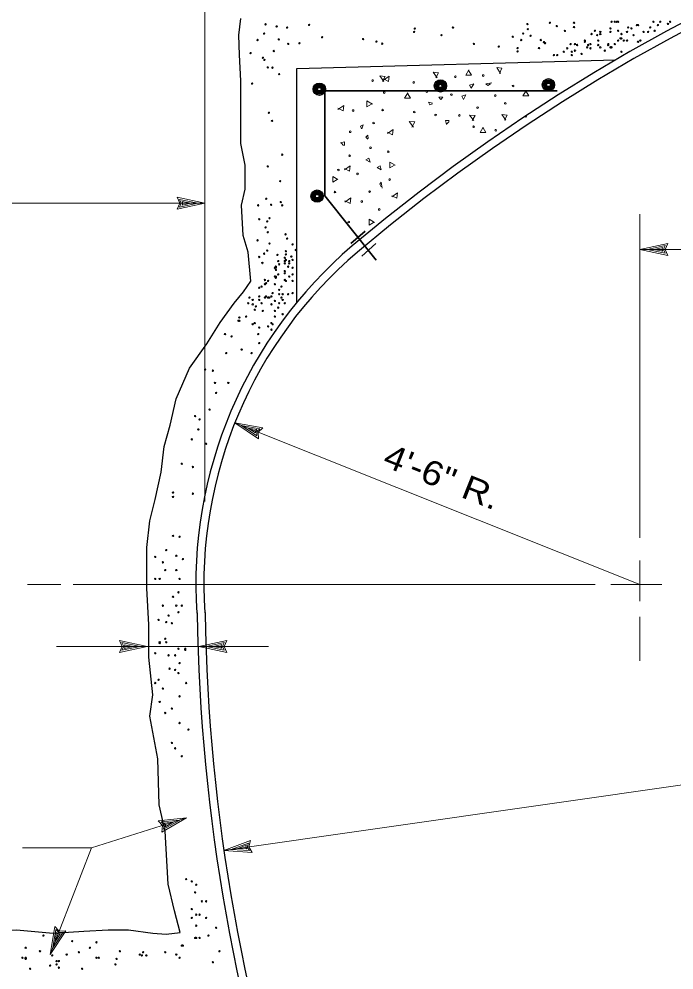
# Model space of a CAD drawing. Extents: x -24.3 to 17.7, y -17.6 to 12.4.
# Drawn here: x -17.912 to -14.525, y -10.053 to -5.135 of the extents above; entities that cross this region are included whole.
import ezdxf
from ezdxf.enums import TextEntityAlignment as Align

# ---------------------------------------------------------------- set-up
doc = ezdxf.new("R2010")
doc.units = 0
doc.header["$LTSCALE"] = 0.05
doc.layers.add('1', color=7, linetype='Continuous', lineweight=13)
doc.layers.add('2', color=7, linetype='Continuous', lineweight=13)

msp = doc.modelspace()

# ---------------------------------------------------------------- linework, layer by layer
at = {"layer": '1'}
for p, q in [((-16.95069, -7.6306), (-16.95069, -1.0886)), ((-19.95069, -6.0876), (-16.95069, -6.0876)), ((-16.95069, -6.0876), (-17.09469, -6.0566)), ((-16.95069, -6.0876), (-17.09469, -6.1186)), ((-16.98769, -6.0876), (-17.08169, -6.0676)), ((-17.07269, -6.0876), (-17.08169, -6.0676)), ((-16.98769, -6.0876), (-17.08169, -6.1076)), ((-17.08169, -6.1076), (-17.07269, -6.0876)), ((-17.02369, -6.0876), (-17.06869, -6.0786)), ((-17.06469, -6.0876), (-17.06869, -6.0786)), ((-17.02369, -6.0876), (-17.06869, -6.0976)), ((-17.06869, -6.0976), (-17.06469, -6.0876)), ((-14.70069, -7.8176), (-14.70069, -6.1446)), ((-14.70069, -6.3266), (-14.55669, -6.2956)), ((-14.70069, -6.3266), (-9.90769, -6.3266)), ((-14.70069, -6.3266), (-14.55669, -6.3576)), ((-14.66369, -6.3266), (-14.56969, -6.3066)), ((-14.66369, -6.3266), (-14.56969, -6.3466)), ((-14.62769, -6.3266), (-14.58269, -6.3166)), ((-14.62769, -6.3266), (-14.58269, -6.3356)), ((-14.58269, -6.3166), (-14.58669, -6.3266)), ((-14.58669, -6.3266), (-14.58269, -6.3356)), ((-14.56969, -6.3066), (-14.57869, -6.3266)), ((-14.57869, -6.3266), (-14.56969, -6.3466)), ((-16.79569, -7.2236), (-16.67369, -7.3056)), ((-16.76169, -7.2376), (-16.66669, -7.2536)), ((-16.76169, -7.2376), (-16.68169, -7.2906)), ((-16.72769, -7.2506), (-16.68969, -7.2756)), ((-16.72769, -7.2506), (-16.68269, -7.2576)), ((-16.68269, -7.2576), (-16.68969, -7.2656)), ((-16.68969, -7.2656), (-16.68969, -7.2756)), ((-16.66669, -7.2536), (-16.68269, -7.2686)), ((-16.68269, -7.2686), (-16.68169, -7.2906)), ((-14.70069, -8.1456), (-14.70069, -7.9356)), ((-17.86769, -8.0586), (-17.69669, -8.0586)), ((-17.63269, -8.0586), (-14.93269, -8.0586)), ((-14.85069, -8.0586), (-14.58769, -8.0586)), ((-14.70069, -8.4546), (-14.70069, -8.2266)), ((-17.24869, -8.3796), (-17.39269, -8.3486)), ((-17.28569, -8.3796), (-17.37969, -8.3596)), ((-17.37069, -8.3796), (-17.37969, -8.3596)), ((-16.98169, -8.3796), (-16.83769, -8.3486)), ((-16.94469, -8.3796), (-16.85069, -8.3596)), ((-16.85069, -8.3596), (-16.85969, -8.3796)), ((-17.24869, -8.3796), (-17.39269, -8.4106)), ((-17.28569, -8.3796), (-17.37969, -8.3996)), ((-17.37969, -8.3996), (-17.37069, -8.3796)), ((-17.32169, -8.3796), (-17.36669, -8.3706)), ((-17.36269, -8.3796), (-17.36669, -8.3706)), ((-17.32169, -8.3796), (-17.36669, -8.3896)), ((-17.36669, -8.3896), (-17.36269, -8.3796)), ((-16.98169, -8.3796), (-16.83769, -8.4106)), ((-16.94469, -8.3796), (-16.85069, -8.3996)), ((-16.90869, -8.3796), (-16.86369, -8.3696)), ((-16.90869, -8.3796), (-16.86369, -8.3886)), ((-16.86369, -8.3696), (-16.86769, -8.3796)), ((-16.86769, -8.3796), (-16.86369, -8.3886)), ((-16.85969, -8.3796), (-16.85069, -8.3996)), ((-17.04569, -9.2666), (-17.19269, -9.2806)), ((-17.08069, -9.2776), (-17.17669, -9.2866)), ((-17.16169, -9.3036), (-17.17669, -9.2866)), ((-17.08069, -9.2776), (-17.16469, -9.3246)), ((-17.11569, -9.2886), (-17.16069, -9.2936)), ((-17.15469, -9.3006), (-17.16069, -9.2936)), ((-17.11569, -9.2886), (-17.15569, -9.3116)), ((-17.16469, -9.3246), (-17.16169, -9.3036)), ((-17.15569, -9.3116), (-17.15469, -9.3006)), ((-16.85269, -9.4346), (-16.70569, -9.4446)), ((-16.81569, -9.4296), (-16.72569, -9.3966)), ((-16.81569, -9.4296), (-16.71969, -9.4356)), ((-16.78069, -9.4246), (-16.73769, -9.4076)), ((-16.78069, -9.4246), (-16.73469, -9.4266)), ((-16.73769, -9.4076), (-16.73969, -9.4186)), ((-16.73969, -9.4186), (-16.73469, -9.4266)), ((-16.72569, -9.3966), (-16.73169, -9.4176)), ((-16.73169, -9.4176), (-16.71969, -9.4356)), ((-17.75069, -9.9726), (-17.72769, -9.8276)), ((-17.75069, -9.9726), (-17.66969, -9.8496)), ((-17.73769, -9.9386), (-17.72169, -9.8436)), ((-17.73769, -9.9386), (-17.68469, -9.8576)), ((-17.72469, -9.9046), (-17.71769, -9.8586)), ((-17.72469, -9.9046), (-17.69969, -9.8656)), ((-17.72169, -9.8436), (-17.70669, -9.8586)), ((-17.71769, -9.8586), (-17.70969, -9.8666)), ((-17.70969, -9.8666), (-17.69969, -9.8656)), ((-17.70669, -9.8586), (-17.68469, -9.8576))]:
    msp.add_line(p, q, dxfattribs=at)
at = {"layer": '1', "lineweight": 35}
for p, q in [((-16.19569, -6.2966), (-16.12269, -6.2326)), ((-16.13969, -6.3606), (-16.06669, -6.2966))]:
    msp.add_line(p, q, dxfattribs=at)
at = {"layer": '1', "lineweight": 25}
for points in [[(-16.71369, -6.4906), (-16.72769, -6.3406), (-16.75369, -6.2546), (-16.76069, -6.0976), (-16.74269, -6.0156), (-16.74269, -5.8916), (-16.76469, -5.7796), (-16.76469, -5.6936), (-16.76469, -5.5816), (-16.76469, -5.4546), (-16.77269, -5.3196), (-16.77569, -5.2186), (-16.76469, -5.1326)], [(-16.47469, -6.5996), (-16.47469, -5.3916), (-14.82469, -5.3466)], [(-17.07869, -9.8596), (-17.10869, -9.7466), (-17.14069, -9.6096), (-17.15669, -9.3356), (-17.18769, -9.1986), (-17.19369, -8.9616), (-17.23569, -8.7406), (-17.21969, -8.6306), (-17.24069, -8.4356), (-17.24069, -8.2676), (-17.25169, -8.0776), (-17.25169, -7.9776), (-17.25169, -7.8676), (-17.23569, -7.7306), (-17.20869, -7.6196), (-17.17769, -7.4776), (-17.16169, -7.3456), (-17.13069, -7.2356), (-17.09869, -7.0986), (-17.03069, -6.9406), (-16.94069, -6.8146), (-16.87269, -6.7036), (-16.79869, -6.6036), (-16.75169, -6.5456), (-16.71369, -6.4906)], [(-18.19469, -11.2756), (-18.20969, -11.1096), (-18.20969, -10.9256), (-18.19869, -10.8466), (-18.18269, -10.6826), (-18.19369, -10.5566), (-18.18269, -10.3986), (-18.19369, -10.2146), (-18.19869, -10.0566), (-18.19369, -9.9406), (-18.19369, -9.8546), (-18.06669, -9.8546), (-17.92469, -9.8456), (-17.73569, -9.8616), (-17.57769, -9.8516), (-17.45169, -9.8456), (-17.34569, -9.8456), (-17.21969, -9.8616), (-17.15169, -9.8676), (-17.07869, -9.8596)]]:
    msp.add_lwpolyline(points, dxfattribs=at)
at = {"layer": '1', "lineweight": 35}
msp.add_lwpolyline([(-15.12869, -5.5066), (-16.32969, -5.5066), (-16.32969, -6.0486), (-16.06469, -6.3826)], dxfattribs=at)
at = {"layer": '1'}
for points in [[(-17.09469, -6.1186), (-17.08069, -6.0876), (-17.09469, -6.0566)], [(-14.55669, -6.2956), (-14.57069, -6.3266), (-14.55669, -6.3576)], [(-14.70069, -8.0586), (-16.79569, -7.2236), (-16.65069, -7.2486)], [(-16.65069, -7.2486), (-16.67469, -7.2716), (-16.67369, -7.3056)], [(-7.03769, -8.0296), (-16.85269, -9.4346), (-16.71469, -9.3836)], [(-17.39269, -8.4106), (-17.37869, -8.3796), (-17.39269, -8.3486)], [(-16.83769, -8.3486), (-16.85169, -8.3796), (-16.83769, -8.4106)], [(-17.71769, -8.3796), (-17.24869, -8.3796), (-16.98169, -8.3796), (-16.62169, -8.3796)], [(-17.53669, -9.4206), (-17.04569, -9.2666), (-17.17369, -9.3396)], [(-17.17369, -9.3396), (-17.16969, -9.3056), (-17.19269, -9.2806)], [(-16.71469, -9.3836), (-16.72369, -9.4166), (-16.70569, -9.4446)], [(-17.89369, -9.4206), (-17.53669, -9.4206), (-17.75069, -9.9726)], [(-17.72769, -9.8276), (-17.70369, -9.8516), (-17.66969, -9.8496)]]:
    msp.add_lwpolyline(points, dxfattribs=at)
for centre in [(-16.63669, -5.1626), (-16.41169, -5.1656), (-15.28269, -5.1616), (-15.16669, -5.1546), (-15.04169, -5.1546), (-14.84769, -5.1496), (-14.83069, -5.1496), (-14.81969, -5.1496), (-14.81369, -5.1496), (-14.81369, -5.1496), (-14.71669, -5.1666), (-14.71069, -5.1666), (-14.63069, -5.1496), (-14.60769, -5.1666), (-14.59569, -5.1496), (-14.55569, -5.1606), (-14.54469, -5.1496), (-16.64469, -5.2106), (-16.57969, -5.1736), (-16.52569, -5.1796), (-15.86869, -5.2016), (-15.86569, -5.1846), (-15.66769, -5.1796), (-15.30469, -5.2106), (-15.28069, -5.1876), (-15.13069, -5.1716), (-15.08869, -5.1966), (-15.04169, -5.1766), (-14.95069, -5.2126), (-14.93369, -5.1956), (-14.90569, -5.2016), (-14.90569, -5.2126), (-14.85369, -5.1836), (-14.85369, -5.2016), (-14.81369, -5.1956), (-14.79669, -5.2126), (-14.76769, -5.2016), (-14.76169, -5.1786), (-14.74469, -5.1836), (-14.68169, -5.2016), (-14.65869, -5.2016), (-14.64769, -5.1786), (-14.64769, -5.1786), (-14.62469, -5.1956), (-16.67869, -5.2436), (-16.56869, -5.2406), (-16.51969, -5.2636), (-16.46169, -5.2606), (-16.34469, -5.2296), (-16.13269, -5.2386), (-16.06369, -5.2516), (-16.03369, -5.2626), (-15.72769, -5.2186), (-15.55969, -5.2636), (-15.35869, -5.2266), (-15.31469, -5.2436), (-15.26669, -5.2216), (-15.21369, -5.2436), (-15.19769, -5.2546), (-15.19169, -5.2606), (-15.05969, -5.2646), (-15.03669, -5.2646), (-14.98569, -5.2466), (-14.98569, -5.2526), (-14.95669, -5.2646), (-14.92269, -5.2186), (-14.91669, -5.2466), (-14.86469, -5.2646), (-14.83069, -5.2646), (-14.81369, -5.2466), (-14.80169, -5.2356), (-14.79669, -5.2356), (-14.78469, -5.2466), (-14.76769, -5.2466), (-14.73369, -5.2186), (-14.71069, -5.2526), (-14.69869, -5.2466), (-16.71469, -5.3116), (-16.59469, -5.3006), (-15.43069, -5.2776), (-15.33369, -5.2856), (-15.33369, -5.3026), (-15.22269, -5.2856), (-15.09469, -5.3046), (-15.07669, -5.2866), (-15.05369, -5.3046), (-15.03669, -5.2986), (-15.02569, -5.2696), (-14.97369, -5.2816), (-14.96869, -5.2696), (-14.95669, -5.2866), (-14.91669, -5.2696), (-14.90569, -5.2816), (-14.88269, -5.2986), (-14.86469, -5.2696), (-14.85369, -5.2816), (-14.84769, -5.2816), (-14.79669, -5.3046), (-16.65069, -5.3356), (-16.64269, -5.3466), (-15.14569, -5.3216), (-15.12869, -5.3216), (-15.05369, -5.3216), (-15.00269, -5.3156), (-16.62569, -5.3856), (-16.60169, -5.3866), (-16.56669, -5.4196), (-16.70669, -5.4686), (-16.61969, -5.6196), (-16.60369, -5.6616), (-16.55069, -5.8366), (-16.62569, -5.8976), (-16.56169, -5.9736), (-16.67569, -6.0986), (-16.63369, -6.0646), (-16.60869, -6.0956), (-16.55869, -6.0816), (-16.55069, -6.0986), (-16.66969, -6.1706), (-16.62869, -6.1816), (-16.61669, -6.1656), (-16.63669, -6.2126), (-16.62569, -6.2376), (-16.53369, -6.2486), (-16.67869, -6.2796), (-16.61669, -6.2966), (-16.52569, -6.2706), (-16.62869, -6.3326), (-16.53169, -6.3356), (-16.49769, -6.3006), (-16.48069, -6.3296), (-16.66969, -6.3656), (-16.64469, -6.3486), (-16.57569, -6.3546), (-16.57169, -6.3866), (-16.53769, -6.3696), (-16.53769, -6.3866), (-16.53169, -6.3526), (-16.53169, -6.3806), (-16.51469, -6.3866), (-16.50369, -6.3636), (-16.49769, -6.3806), (-16.65369, -6.3966), (-16.58869, -6.4216), (-16.58369, -6.4156), (-16.58369, -6.4216), (-16.58369, -6.4326), (-16.56669, -6.4036), (-16.53769, -6.3986), (-16.53769, -6.4386), (-16.52069, -6.4156), (-16.51469, -6.3986), (-16.49769, -6.4216), (-16.64069, -6.4846), (-16.62369, -6.4896), (-16.58869, -6.4666), (-16.58369, -6.4666), (-16.58369, -6.4726), (-16.57169, -6.4556), (-16.53769, -6.4496), (-16.53769, -6.4846), (-16.53169, -6.4896), (-16.51469, -6.4666), (-16.49769, -6.4556), (-16.49769, -6.4896), (-16.66969, -6.5246), (-16.65769, -6.5186), (-16.64069, -6.5066), (-16.63469, -6.5016), (-16.63469, -6.5016), (-16.58869, -6.5066), (-16.56669, -6.5356), (-16.55469, -6.5186), (-16.72069, -6.5756), (-16.70369, -6.5876), (-16.66969, -6.5696), (-16.66969, -6.5876), (-16.64069, -6.5756), (-16.63469, -6.5696), (-16.62369, -6.5756), (-16.61769, -6.5756), (-16.60669, -6.5696), (-16.60069, -6.5526), (-16.58869, -6.5926), (-16.56669, -6.5586), (-16.55469, -6.5756), (-16.54869, -6.5586), (-16.54869, -6.5876), (-16.52069, -6.5586), (-16.49769, -6.5526), (-16.72669, -6.6046), (-16.70369, -6.6106), (-16.69269, -6.6386), (-16.68669, -6.6216), (-16.65769, -6.6046), (-16.60669, -6.6106), (-16.57169, -6.6276), (-16.56669, -6.6046), (-16.53769, -6.6046), (-16.77269, -6.6786), (-16.73769, -6.6736), (-16.65169, -6.6446), (-16.58869, -6.6446), (-16.58869, -6.6736), (-16.54869, -6.6616), (-16.77769, -6.6956), (-16.77269, -6.6956), (-16.70369, -6.7136), (-16.69269, -6.7076), (-16.66969, -6.7306), (-16.62369, -6.7246), (-16.60669, -6.7076), (-16.60069, -6.7136), (-16.84669, -6.7646), (-16.81269, -6.7766), (-16.67469, -6.7646), (-16.60669, -6.7416), (-16.66969, -6.8106), (-16.84069, -6.8626), (-16.76069, -6.8446), (-16.70969, -6.8626), (-16.94969, -6.9476), (-16.90969, -6.9536), (-16.89869, -7.0166), (-16.82969, -7.0166), (-16.89269, -7.0686), (-16.92669, -7.1546), (-17.00169, -7.1886), (-16.97869, -7.2056), (-16.98469, -7.2576), (-17.01869, -7.3086), (-16.94469, -7.3316), (-17.07069, -7.4346), (-17.01269, -7.4516), (-17.11569, -7.5836), (-17.11569, -7.6066), (-17.01269, -7.5896), (-17.11569, -7.8076), (-17.08169, -7.8126), (-17.20769, -7.9166), (-17.15069, -7.8816), (-17.09869, -7.9106), (-17.16769, -7.9446), (-17.06469, -7.9276), (-17.15569, -7.9846), (-17.09869, -7.9846), (-17.20769, -8.0306), (-17.18469, -8.0306), (-17.08169, -8.0306), (-17.08769, -8.0996), (-17.11569, -8.1226), (-17.16769, -8.1686), (-17.09869, -8.1686), (-17.08769, -8.2026), (-17.07069, -8.1686), (-17.19069, -8.2426), (-17.15069, -8.2536), (-17.13869, -8.2196), (-17.12169, -8.2596), (-17.18469, -8.3576), (-17.18469, -8.3626), (-17.15569, -8.3396), (-17.15069, -8.3576), (-17.08769, -8.3916), (-17.05269, -8.3916), (-17.05269, -8.3976), (-17.20769, -8.4146), (-17.13869, -8.4256), (-17.10469, -8.4256), (-17.13369, -8.4946), (-17.10469, -8.5006), (-17.08169, -8.4656), (-17.19069, -8.5516), (-17.08769, -8.5176), (-17.20769, -8.5686), (-17.16769, -8.5976), (-17.04769, -8.5686), (-17.08169, -8.6376), (-17.18469, -8.6666), (-17.12169, -8.7006), (-17.15569, -8.7236), (-17.08169, -8.7756), (-17.03569, -8.8096), (-17.12169, -8.8786), (-17.10469, -8.9066), (-17.07069, -8.9476), (-17.04769, -9.5826), (-17.01869, -9.5946), (-16.99569, -9.6116), (-17.00169, -9.6516), (-17.01869, -9.7376), (-16.96669, -9.6976), (-16.94469, -9.6976), (-17.01869, -9.7836), (-16.99569, -9.7666), (-16.97869, -9.7666), (-16.94469, -9.7836), (-16.99569, -9.8236), (-16.89269, -9.8346), (-17.78569, -9.8746), (-17.00169, -9.8866), (-16.99569, -9.8866), (-16.97869, -9.8866), (-16.93269, -9.8746), (-17.63769, -9.9036), (-17.51169, -9.9096), (-17.07069, -9.9266), (-17.06469, -9.9266), (-17.87769, -9.9376), (-17.80369, -9.9556), (-17.74069, -9.9776), (-17.66569, -9.9726), (-17.60269, -9.9606), (-17.54569, -9.9376), (-17.39069, -9.9556), (-17.28769, -9.9726), (-17.27669, -9.9776), (-17.27069, -9.9606), (-17.25369, -9.9776), (-17.15569, -9.9606), (-17.09869, -9.9726), (-16.87569, -9.9556), (-17.89469, -9.9896), (-17.87769, -9.9896), (-17.87769, -9.9956), (-17.75169, -10.0296), (-17.71769, -10.0066), (-17.71769, -10.0236), (-17.70569, -10.0066), (-17.51169, -9.9896), (-17.49969, -9.9896), (-17.41369, -10.0236), (-17.40769, -9.9956), (-17.08169, -9.9896), (-16.90969, -10.0126), (-17.85469, -10.0466), (-17.70569, -10.0406), (-17.58569, -10.0466)]:
    msp.add_circle(centre, 0.00361, dxfattribs=at)
at = {"layer": '1', "lineweight": 25}
for centre, radius in [((-15.73256, -5.48103), 0.0319), ((-15.73256, -5.48103), 0.02658), ((-15.17394, -5.4754), 0.0319), ((-15.17394, -5.4754), 0.02658), ((-15.17394, -5.4754), 0.02215), ((-15.17394, -5.4754), 0.01846), ((-16.35888, -5.49794), 0.0319), ((-16.35888, -5.49794), 0.02658), ((-16.35888, -5.49794), 0.02215), ((-16.35888, -5.49794), 0.01846), ((-16.35888, -5.49794), 0.01538), ((-16.35888, -5.49794), 0.01282), ((-16.35888, -5.49794), 0.01068), ((-16.35888, -5.49794), 0.0089), ((-15.73256, -5.48103), 0.02215), ((-15.73256, -5.48103), 0.01846), ((-15.73256, -5.48103), 0.01538), ((-15.73256, -5.48103), 0.01282), ((-15.73256, -5.48103), 0.01068), ((-15.73256, -5.48103), 0.0089), ((-15.17394, -5.4754), 0.01538), ((-15.17394, -5.4754), 0.01282), ((-15.17394, -5.4754), 0.01068), ((-15.17394, -5.4754), 0.0089), ((-16.37018, -6.05093), 0.0319), ((-16.37018, -6.05093), 0.02658), ((-16.37018, -6.05093), 0.02215), ((-16.37018, -6.05093), 0.01846), ((-16.37018, -6.05093), 0.01538), ((-16.37018, -6.05093), 0.01282), ((-16.37018, -6.05093), 0.01068), ((-16.37018, -6.05093), 0.0089)]:
    msp.add_circle(centre, radius, dxfattribs=at)
for centre, radius, start, end in [((-9.90906, -13.7666), 9.74984, 49.71979, 130.09764), ((-9.90906, -13.7666), 9.70818, 49.71979, 130.09764), ((-14.70065, -8.05836), 2.29713, 130.38466, 183.72825), ((-14.70065, -8.05836), 2.25547, 130.38466, 183.72825), ((-7.24244, -8.05836), 9.74984, 180.86487, 199.33073), ((-7.24244, -8.05836), 9.70818, 180.86487, 199.33073)]:
    msp.add_arc(centre, radius, start, end, dxfattribs=at)
at = {"layer": '2'}
for p, q in [((-15.68669, -5.6656), (-15.70169, -5.6786)), ((-16.23369, -5.7896), (-16.24669, -5.7746))]:
    msp.add_line(p, q, dxfattribs=at)
for points in [[(-15.58569, -5.4026), (-15.57169, -5.4256), (-15.60169, -5.4256), (-15.58569, -5.3986)], [(-15.42769, -5.4166), (-15.41469, -5.3896), (-15.44169, -5.3866), (-15.42169, -5.4166)], [(-16.03169, -5.4586), (-16.01869, -5.4326), (-16.04569, -5.4296), (-16.02569, -5.4586)], [(-16.02669, -5.4446), (-16.00069, -5.4576), (-15.99769, -5.4306), (-16.02669, -5.4506)], [(-15.75569, -5.4386), (-15.74269, -5.4126), (-15.76969, -5.4096), (-15.74969, -5.4386)], [(-15.47369, -5.4706), (-15.48669, -5.4786), (-15.49769, -5.4706), (-15.46669, -5.4656)], [(-15.28969, -5.5106), (-15.27569, -5.5326), (-15.30569, -5.5326), (-15.28969, -5.5056)], [(-15.90169, -5.5216), (-15.88769, -5.5446), (-15.91769, -5.5446), (-15.90169, -5.5166)], [(-15.71969, -5.5396), (-15.72969, -5.5506), (-15.74069, -5.5396), (-15.72269, -5.5376)], [(-16.26269, -5.5966), (-16.23569, -5.6106), (-16.23269, -5.5826), (-16.26269, -5.6036)], [(-16.08969, -5.5746), (-16.11269, -5.5886), (-16.11269, -5.5586), (-16.08469, -5.5746)], [(-15.77369, -5.5736), (-15.78769, -5.5786), (-15.79369, -5.5646), (-15.77369, -5.5706)], [(-15.56769, -5.6606), (-15.55369, -5.6346), (-15.58169, -5.6316), (-15.56069, -5.6606)], [(-15.40169, -5.6586), (-15.38769, -5.6316), (-15.41569, -5.6286), (-15.39469, -5.6586)], [(-16.14169, -5.7026), (-16.14669, -5.6886), (-16.13269, -5.6826), (-16.13869, -5.7026)], [(-15.87969, -5.6946), (-15.86569, -5.6676), (-15.89369, -5.6646), (-15.87269, -5.6946)], [(-15.70169, -5.6806), (-15.70669, -5.6606), (-15.68669, -5.6606)], [(-15.51169, -5.6986), (-15.49769, -5.7216), (-15.52769, -5.7216), (-15.51169, -5.6946)], [(-16.10769, -5.7566), (-16.11869, -5.7466), (-16.10769, -5.7356), (-16.10569, -5.7536)], [(-16.00669, -5.7206), (-15.98069, -5.7336), (-15.97769, -5.7066), (-16.00669, -5.7266)], [(-16.24869, -5.7746), (-16.22869, -5.7696), (-16.22869, -5.7896)], [(-16.22869, -5.9086), (-16.20269, -5.9226), (-16.19969, -5.8946), (-16.22869, -5.9156)], [(-15.97069, -5.8906), (-15.99369, -5.9046), (-15.99369, -5.8746), (-15.96669, -5.8906)], [(-16.26669, -5.9646), (-16.28969, -5.9786), (-16.28969, -5.9486), (-16.26269, -5.9646)], [(-16.03869, -6.0026), (-16.04669, -5.9896), (-16.03869, -5.9786), (-16.03369, -6.0096)], [(-15.98469, -6.0486), (-15.95769, -6.0616), (-15.95469, -6.0346), (-15.98469, -6.0546)], [(-16.22669, -6.0746), (-16.19969, -6.0886), (-16.19669, -6.0606), (-16.22669, -6.0816)], [(-16.07869, -6.1866), (-16.10069, -6.2006), (-16.10069, -6.1706), (-16.07369, -6.1866)]]:
    msp.add_lwpolyline(points, dxfattribs=at)
for points in [[(-15.56069, -5.4706), (-15.57369, -5.4926), (-15.58169, -5.4766)], [(-15.60069, -5.5276), (-15.61369, -5.5506), (-15.62169, -5.5346)], [(-16.09569, -5.8756), (-16.11869, -5.8626), (-16.10269, -5.8546)], [(-16.03869, -5.9156), (-16.06069, -5.9026), (-16.04469, -5.8946)]]:
    msp.add_lwpolyline(points, close=True, dxfattribs=at)
for centre in [(-16.08342, -5.45307), (-15.65543, -5.43399), (-15.51143, -5.42732), (-15.87076, -5.46332), (-15.80343, -5.51065), (-15.35677, -5.48132), (-16.02342, -5.51532), (-15.67543, -5.52598), (-15.44877, -5.53065), (-16.18409, -5.6084), (-16.03142, -5.60573), (-15.54076, -5.59332), (-15.39743, -5.57132), (-15.86809, -5.61598), (-15.75809, -5.63132), (-15.63476, -5.63398), (-15.29143, -5.63865), (-16.07876, -5.67307), (-15.56076, -5.69198), (-16.19942, -5.7184), (-15.44677, -5.70998), (-16.09409, -5.80106), (-16.20209, -5.84173), (-16.00209, -5.82106), (-16.26009, -5.91573), (-16.16142, -5.93573), (-15.99542, -5.96506), (-16.27809, -6.02973), (-16.09876, -6.02773), (-16.13942, -6.07906), (-16.04942, -6.11973), (-16.20675, -6.18506)]:
    msp.add_circle(centre, 0.00433, dxfattribs=at)

# ---------------------------------------------------------------- texts
at = {"layer": '1', "width": 1.15}
msp.add_text('4\'-6" R.', height=0.125, rotation=338.263, dxfattribs=at).set_placement((-15.74638, -7.56004), align=Align.CENTER)

doc.saveas('drawing.dxf')
